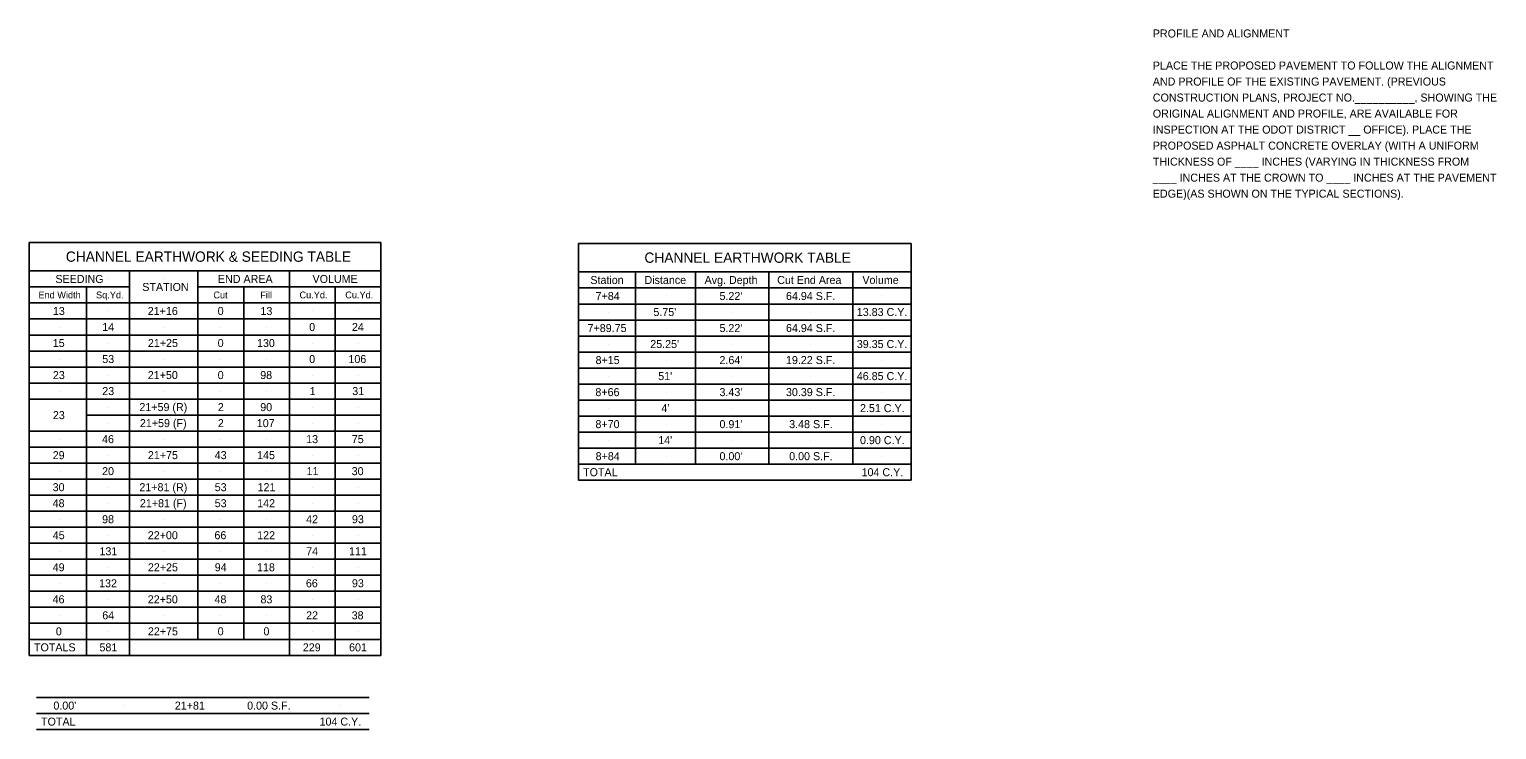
# Model space of a CAD drawing. Extents: x -30 to 76, y -31 to 50.
# Drawn here: x -29.08 to -3.41, y -12.95 to -0.71 of the extents above; entities that cross this region are included whole.
import ezdxf

# ---------------------------------------------------------------- set-up
doc = ezdxf.new("R2010")
doc.units = 0
doc.layers.add('SH_Data', color=7, linetype='Continuous')
doc.layers.add('SH_Text', color=7, linetype='Continuous')

msp = doc.modelspace()

# ---------------------------------------------------------------- linework, layer by layer
at = {"layer": 'SH_Data'}
for p, q in [((-29.076, -11.653), (-29.076, -4.433)), ((-29.076, -4.433), (-22.926, -4.433)), ((-22.926, -11.653), (-22.926, -4.433)), ((-19.47, -8.591), (-19.47, -4.451)), ((-19.47, -4.451), (-13.648, -4.451)), ((-13.648, -8.591), (-13.648, -4.451)), ((-22.926, -4.933), (-29.076, -4.933)), ((-28.707, -5.073), (-28.707, -5.073)), ((-27.692, -5.073), (-27.692, -5.073)), ((-27.326, -11.653), (-27.326, -4.933)), ((-26.726, -5.073), (-26.726, -5.073)), ((-26.126, -11.373), (-26.126, -4.933)), ((-25.326, -5.073), (-25.326, -5.073)), ((-24.526, -11.653), (-24.526, -4.933)), ((-13.648, -4.951), (-19.47, -4.951)), ((-18.951, -5.091), (-18.951, -5.091)), ((-18.472, -8.311), (-18.472, -4.951)), ((-17.936, -5.091), (-17.936, -5.091)), ((-17.42, -8.311), (-17.42, -4.951)), ((-16.781, -5.091), (-16.781, -5.091)), ((-16.14, -8.311), (-16.14, -4.951)), ((-15.419, -5.091), (-15.419, -5.091)), ((-14.669, -8.311), (-14.669, -4.951)), ((-14.169, -5.091), (-14.169, -5.091)), ((-27.326, -5.213), (-29.076, -5.213)), ((-28.557, -5.353), (-28.557, -5.353)), ((-28.077, -11.653), (-28.077, -5.213)), ((-27.692, -5.353), (-27.692, -5.353)), ((-26.726, -5.353), (-26.726, -5.353)), ((-22.926, -5.213), (-26.126, -5.213)), ((-25.326, -11.373), (-25.326, -5.213)), ((-25.025, -5.353), (-25.025, -5.353)), ((-23.726, -11.653), (-23.726, -5.213)), ((-23.425, -5.353), (-23.425, -5.353)), ((-13.648, -5.231), (-19.47, -5.231)), ((-18.951, -5.371), (-18.951, -5.371)), ((-17.936, -5.371), (-17.936, -5.371)), ((-16.781, -5.371), (-16.781, -5.371)), ((-15.419, -5.371), (-15.419, -5.371)), ((-14.169, -5.371), (-14.169, -5.371)), ((-22.926, -5.493), (-29.076, -5.493)), ((-28.557, -5.633), (-28.557, -5.633)), ((-27.692, -5.633), (-27.692, -5.633)), ((-26.726, -5.633), (-26.726, -5.633)), ((-25.726, -5.633), (-25.726, -5.633)), ((-24.926, -5.633), (-24.926, -5.633)), ((-24.126, -5.633), (-24.126, -5.633)), ((-23.326, -5.633), (-23.326, -5.633)), ((-13.648, -5.511), (-19.47, -5.511)), ((-22.926, -5.773), (-29.076, -5.773)), ((-13.648, -5.791), (-19.47, -5.791)), ((-18.951, -5.651), (-18.951, -5.651)), ((-17.936, -5.651), (-17.936, -5.651)), ((-16.781, -5.651), (-16.781, -5.651)), ((-15.419, -5.651), (-15.419, -5.651)), ((-14.169, -5.651), (-14.169, -5.651)), ((-22.926, -6.053), (-29.076, -6.053)), ((-28.557, -5.913), (-28.557, -5.913)), ((-27.692, -5.913), (-27.692, -5.913)), ((-26.726, -5.913), (-26.726, -5.913)), ((-25.726, -5.913), (-25.726, -5.913)), ((-24.926, -5.913), (-24.926, -5.913)), ((-24.126, -5.913), (-24.126, -5.913)), ((-23.326, -5.913), (-23.326, -5.913)), ((-13.648, -6.071), (-19.47, -6.071)), ((-18.951, -5.931), (-18.951, -5.931)), ((-17.936, -5.931), (-17.936, -5.931)), ((-16.781, -5.931), (-16.781, -5.931)), ((-15.419, -5.931), (-15.419, -5.931)), ((-14.169, -5.931), (-14.169, -5.931)), ((-22.926, -6.333), (-29.076, -6.333)), ((-28.557, -6.193), (-28.557, -6.193)), ((-27.692, -6.193), (-27.692, -6.193)), ((-26.726, -6.193), (-26.726, -6.193)), ((-25.726, -6.193), (-25.726, -6.193)), ((-24.926, -6.193), (-24.926, -6.193)), ((-24.126, -6.193), (-24.126, -6.193)), ((-23.326, -6.193), (-23.326, -6.193)), ((-13.648, -6.351), (-19.47, -6.351)), ((-18.951, -6.211), (-18.951, -6.211)), ((-17.936, -6.211), (-17.936, -6.211)), ((-16.781, -6.211), (-16.781, -6.211)), ((-15.419, -6.211), (-15.419, -6.211)), ((-14.169, -6.211), (-14.169, -6.211)), ((-22.926, -6.613), (-29.076, -6.613)), ((-28.557, -6.473), (-28.557, -6.473)), ((-27.692, -6.473), (-27.692, -6.473)), ((-26.726, -6.473), (-26.726, -6.473)), ((-25.726, -6.473), (-25.726, -6.473)), ((-24.926, -6.473), (-24.926, -6.473)), ((-24.126, -6.473), (-24.126, -6.473)), ((-23.326, -6.473), (-23.326, -6.473)), ((-13.648, -6.631), (-19.47, -6.631)), ((-18.951, -6.491), (-18.951, -6.491)), ((-17.936, -6.491), (-17.936, -6.491)), ((-16.781, -6.491), (-16.781, -6.491)), ((-15.419, -6.491), (-15.419, -6.491)), ((-14.169, -6.491), (-14.169, -6.491)), ((-22.926, -6.893), (-29.076, -6.893)), ((-28.557, -6.753), (-28.557, -6.753)), ((-27.692, -6.753), (-27.692, -6.753)), ((-26.726, -6.753), (-26.726, -6.753)), ((-25.726, -6.753), (-25.726, -6.753)), ((-24.926, -6.753), (-24.926, -6.753)), ((-24.126, -6.753), (-24.126, -6.753)), ((-23.326, -6.753), (-23.326, -6.753)), ((-13.648, -6.911), (-19.47, -6.911)), ((-18.951, -6.771), (-18.951, -6.771)), ((-17.936, -6.771), (-17.936, -6.771)), ((-16.781, -6.771), (-16.781, -6.771)), ((-15.419, -6.771), (-15.419, -6.771)), ((-14.169, -6.771), (-14.169, -6.771)), ((-22.926, -7.173), (-29.076, -7.173)), ((-28.557, -7.033), (-28.557, -7.033)), ((-27.692, -7.033), (-27.692, -7.033)), ((-26.726, -7.033), (-26.726, -7.033)), ((-25.726, -7.033), (-25.726, -7.033)), ((-24.926, -7.033), (-24.926, -7.033)), ((-24.126, -7.033), (-24.126, -7.033)), ((-23.326, -7.033), (-23.326, -7.033)), ((-18.951, -7.051), (-18.951, -7.051)), ((-17.936, -7.051), (-17.936, -7.051)), ((-16.781, -7.051), (-16.781, -7.051)), ((-15.419, -7.051), (-15.419, -7.051)), ((-14.169, -7.051), (-14.169, -7.051)), ((-27.692, -7.313), (-27.692, -7.313)), ((-26.726, -7.313), (-26.726, -7.313)), ((-25.726, -7.313), (-25.726, -7.313)), ((-24.926, -7.313), (-24.926, -7.313)), ((-24.126, -7.313), (-24.126, -7.313)), ((-23.326, -7.313), (-23.326, -7.313)), ((-13.648, -7.191), (-19.47, -7.191)), ((-18.951, -7.331), (-18.951, -7.331)), ((-17.936, -7.331), (-17.936, -7.331)), ((-16.781, -7.331), (-16.781, -7.331)), ((-15.419, -7.331), (-15.419, -7.331)), ((-14.169, -7.331), (-14.169, -7.331)), ((-28.557, -7.453), (-28.557, -7.453)), ((-22.926, -7.453), (-28.077, -7.453)), ((-27.692, -7.593), (-27.692, -7.593)), ((-26.726, -7.593), (-26.726, -7.593)), ((-25.726, -7.593), (-25.726, -7.593)), ((-24.926, -7.593), (-24.926, -7.593)), ((-24.126, -7.593), (-24.126, -7.593)), ((-23.326, -7.593), (-23.326, -7.593)), ((-13.648, -7.471), (-19.47, -7.471)), ((-18.951, -7.611), (-18.951, -7.611)), ((-17.936, -7.611), (-17.936, -7.611)), ((-16.781, -7.611), (-16.781, -7.611)), ((-15.419, -7.611), (-15.419, -7.611)), ((-14.169, -7.611), (-14.169, -7.611)), ((-22.926, -7.733), (-29.076, -7.733)), ((-28.557, -7.873), (-28.557, -7.873)), ((-27.692, -7.873), (-27.692, -7.873)), ((-26.726, -7.873), (-26.726, -7.873)), ((-25.726, -7.873), (-25.726, -7.873)), ((-24.926, -7.873), (-24.926, -7.873)), ((-24.126, -7.873), (-24.126, -7.873)), ((-23.326, -7.873), (-23.326, -7.873)), ((-13.648, -7.751), (-19.47, -7.751)), ((-18.951, -7.891), (-18.951, -7.891)), ((-17.936, -7.891), (-17.936, -7.891)), ((-16.781, -7.891), (-16.781, -7.891)), ((-15.419, -7.891), (-15.419, -7.891)), ((-14.169, -7.891), (-14.169, -7.891)), ((-22.926, -8.013), (-29.076, -8.013)), ((-28.557, -8.153), (-28.557, -8.153)), ((-27.692, -8.153), (-27.692, -8.153)), ((-26.726, -8.153), (-26.726, -8.153)), ((-25.726, -8.153), (-25.726, -8.153)), ((-24.926, -8.153), (-24.926, -8.153)), ((-24.126, -8.153), (-24.126, -8.153)), ((-23.326, -8.153), (-23.326, -8.153)), ((-13.648, -8.031), (-19.47, -8.031)), ((-18.951, -8.171), (-18.951, -8.171)), ((-17.936, -8.171), (-17.936, -8.171)), ((-16.781, -8.171), (-16.781, -8.171)), ((-15.419, -8.171), (-15.419, -8.171)), ((-14.169, -8.171), (-14.169, -8.171)), ((-22.926, -8.293), (-29.076, -8.293)), ((-28.557, -8.433), (-28.557, -8.433)), ((-27.692, -8.433), (-27.692, -8.433)), ((-26.726, -8.433), (-26.726, -8.433)), ((-25.726, -8.433), (-25.726, -8.433)), ((-24.926, -8.433), (-24.926, -8.433)), ((-24.126, -8.433), (-24.126, -8.433)), ((-23.326, -8.433), (-23.326, -8.433)), ((-13.648, -8.311), (-19.47, -8.311)), ((-22.926, -8.573), (-29.076, -8.573)), ((-28.557, -8.713), (-28.557, -8.713)), ((-27.692, -8.713), (-27.692, -8.713)), ((-26.726, -8.713), (-26.726, -8.713)), ((-25.726, -8.713), (-25.726, -8.713)), ((-24.926, -8.713), (-24.926, -8.713)), ((-24.126, -8.713), (-24.126, -8.713)), ((-23.326, -8.713), (-23.326, -8.713)), ((-13.648, -8.591), (-19.47, -8.591)), ((-22.926, -8.853), (-29.076, -8.853)), ((-22.926, -9.133), (-29.076, -9.133)), ((-28.557, -8.993), (-28.557, -8.993)), ((-27.692, -8.993), (-27.692, -8.993)), ((-26.726, -8.993), (-26.726, -8.993)), ((-25.726, -8.993), (-25.726, -8.993)), ((-24.926, -8.993), (-24.926, -8.993)), ((-24.126, -8.993), (-24.126, -8.993)), ((-23.326, -8.993), (-23.326, -8.993)), ((-22.926, -9.413), (-29.076, -9.413)), ((-28.557, -9.273), (-28.557, -9.273)), ((-27.692, -9.273), (-27.692, -9.273)), ((-26.726, -9.273), (-26.726, -9.273)), ((-25.726, -9.273), (-25.726, -9.273)), ((-24.926, -9.273), (-24.926, -9.273)), ((-24.126, -9.273), (-24.126, -9.273)), ((-23.326, -9.273), (-23.326, -9.273)), ((-22.926, -9.693), (-29.076, -9.693)), ((-28.557, -9.553), (-28.557, -9.553)), ((-27.692, -9.553), (-27.692, -9.553)), ((-26.726, -9.553), (-26.726, -9.553)), ((-25.726, -9.553), (-25.726, -9.553)), ((-24.926, -9.553), (-24.926, -9.553)), ((-24.126, -9.553), (-24.126, -9.553)), ((-23.326, -9.553), (-23.326, -9.553)), ((-22.926, -9.973), (-29.076, -9.973)), ((-28.557, -9.833), (-28.557, -9.833)), ((-27.692, -9.833), (-27.692, -9.833)), ((-26.726, -9.833), (-26.726, -9.833)), ((-25.726, -9.833), (-25.726, -9.833)), ((-24.926, -9.833), (-24.926, -9.833)), ((-24.126, -9.833), (-24.126, -9.833)), ((-23.326, -9.833), (-23.326, -9.833)), ((-22.926, -10.253), (-29.076, -10.253)), ((-28.557, -10.113), (-28.557, -10.113)), ((-27.692, -10.113), (-27.692, -10.113)), ((-26.726, -10.113), (-26.726, -10.113)), ((-25.726, -10.113), (-25.726, -10.113)), ((-24.926, -10.113), (-24.926, -10.113)), ((-24.126, -10.113), (-24.126, -10.113)), ((-23.326, -10.113), (-23.326, -10.113)), ((-28.557, -10.393), (-28.557, -10.393)), ((-27.692, -10.393), (-27.692, -10.393)), ((-26.726, -10.393), (-26.726, -10.393)), ((-25.726, -10.393), (-25.726, -10.393)), ((-24.926, -10.393), (-24.926, -10.393)), ((-24.126, -10.393), (-24.126, -10.393)), ((-23.326, -10.393), (-23.326, -10.393)), ((-22.926, -10.533), (-29.076, -10.533)), ((-28.557, -10.673), (-28.557, -10.673)), ((-27.692, -10.673), (-27.692, -10.673)), ((-26.726, -10.673), (-26.726, -10.673)), ((-25.726, -10.673), (-25.726, -10.673)), ((-24.926, -10.673), (-24.926, -10.673)), ((-24.126, -10.673), (-24.126, -10.673)), ((-23.326, -10.673), (-23.326, -10.673)), ((-22.926, -10.813), (-29.076, -10.813)), ((-28.557, -10.953), (-28.557, -10.953)), ((-27.692, -10.953), (-27.692, -10.953)), ((-26.726, -10.953), (-26.726, -10.953)), ((-25.726, -10.953), (-25.726, -10.953)), ((-24.926, -10.953), (-24.926, -10.953)), ((-24.126, -10.953), (-24.126, -10.953)), ((-23.326, -10.953), (-23.326, -10.953)), ((-22.926, -11.093), (-29.076, -11.093)), ((-28.557, -11.233), (-28.557, -11.233)), ((-27.692, -11.233), (-27.692, -11.233)), ((-26.726, -11.233), (-26.726, -11.233)), ((-25.726, -11.233), (-25.726, -11.233)), ((-24.926, -11.233), (-24.926, -11.233)), ((-24.126, -11.233), (-24.126, -11.233)), ((-23.326, -11.233), (-23.326, -11.233)), ((-22.926, -11.373), (-29.076, -11.373)), ((-27.692, -11.513), (-27.692, -11.513)), ((-24.126, -11.513), (-24.126, -11.513)), ((-23.326, -11.513), (-23.326, -11.513)), ((-22.926, -11.653), (-29.076, -11.653)), ((-23.13, -12.391), (-28.952, -12.391)), ((-28.433, -12.531), (-28.433, -12.531)), ((-27.418, -12.531), (-27.418, -12.531)), ((-26.263, -12.531), (-26.263, -12.531)), ((-24.901, -12.531), (-24.901, -12.531)), ((-23.651, -12.531), (-23.651, -12.531)), ((-23.13, -12.671), (-28.952, -12.671)), ((-23.13, -12.951), (-28.952, -12.951))]:
    msp.add_line(p, q, dxfattribs=at)

# ---------------------------------------------------------------- texts
for s, height, p in [('CHANNEL EARTHWORK & SEEDING TABLE', 0.18, (-28.437, -4.773)), ('CHANNEL EARTHWORK TABLE', 0.18, (-18.316, -4.791)), ('SEEDING', 0.14, (-28.62, -5.143)), ('END AREA', 0.14, (-25.777, -5.143)), ('VOLUME', 0.14, (-24.122, -5.143)), ('Station', 0.14, (-19.262, -5.161)), ('Distance', 0.14, (-18.315, -5.161)), ('Avg. Depth', 0.14, (-17.264, -5.161)), ('Cut End Area', 0.14, (-15.994, -5.161)), ('Volume', 0.14, (-14.503, -5.161)), ('End Width', 0.12, (-28.917, -5.413)), ('Sq.Yd.', 0.12, (-27.909, -5.413)), ('STATION', 0.14, (-27.1, -5.283)), ('Cut', 0.12, (-25.857, -5.413)), ('Fill', 0.12, (-25.036, -5.413)), ('Cu.Yd.', 0.12, (-24.35, -5.413)), ('Cu.Yd.', 0.12, (-23.55, -5.413)), ('7+84', 0.14, (-19.17, -5.441)), ("5.22'", 0.14, (-17.003, -5.441)), ('64.94 S.F.', 0.14, (-15.84, -5.441)), ('13', 0.14, (-28.664, -5.703)), ('21+16', 0.14, (-27.005, -5.703)), ('0', 0.14, (-25.781, -5.703)), ('13', 0.14, (-25.033, -5.703)), ("5.75'", 0.14, (-18.159, -5.721)), ('13.83 C.Y.', 0.14, (-14.601, -5.721)), ('14', 0.14, (-27.8, -5.983)), ('0', 0.14, (-24.181, -5.983)), ('24', 0.14, (-23.433, -5.983)), ('7+89.75', 0.14, (-19.311, -6.001)), ("5.22'", 0.14, (-17.003, -6.001)), ('64.94 S.F.', 0.14, (-15.84, -6.001)), ('15', 0.14, (-28.666, -6.263)), ('21+25', 0.14, (-27.002, -6.263)), ('0', 0.14, (-25.781, -6.263)), ('130', 0.14, (-25.093, -6.263)), ("25.25'", 0.14, (-18.214, -6.281)), ('39.35 C.Y.', 0.14, (-14.601, -6.281)), ('53', 0.14, (-27.8, -6.543)), ('0', 0.14, (-24.181, -6.543)), ('106', 0.14, (-23.494, -6.543)), ('8+15', 0.14, (-19.171, -6.561)), ("2.64'", 0.14, (-17.003, -6.561)), ('19.22 S.F.', 0.14, (-15.84, -6.561)), ('23', 0.14, (-28.664, -6.823)), ('21+50', 0.14, (-27.004, -6.823)), ('0', 0.14, (-25.781, -6.823)), ('98', 0.14, (-25.037, -6.823)), ("51'", 0.14, (-18.075, -6.841)), ('46.85 C.Y.', 0.14, (-14.601, -6.841)), ('23', 0.14, (-27.8, -7.103)), ('1', 0.14, (-24.172, -7.103)), ('31', 0.14, (-23.427, -7.103)), ('8+66', 0.14, (-19.174, -7.121)), ("3.43'", 0.14, (-17.003, -7.121)), ('30.39 S.F.', 0.14, (-15.84, -7.121)), ('23', 0.14, (-28.664, -7.523)), ('21+59 (R)', 0.14, (-27.151, -7.383)), ('2', 0.14, (-25.778, -7.383)), ('90', 0.14, (-25.037, -7.383)), ("4'", 0.14, (-18.019, -7.401)), ('2.51 C.Y.', 0.14, (-14.545, -7.401)), ('21+59 (F)', 0.14, (-27.142, -7.663)), ('2', 0.14, (-25.778, -7.663)), ('107', 0.14, (-25.097, -7.663)), ('8+70', 0.14, (-19.173, -7.681)), ("0.91'", 0.14, (-17.003, -7.681)), ('3.48 S.F.', 0.14, (-15.784, -7.681)), ('46', 0.14, (-27.804, -7.943)), ('13', 0.14, (-24.233, -7.943)), ('75', 0.14, (-23.435, -7.943)), ("14'", 0.14, (-18.075, -7.961)), ('0.90 C.Y.', 0.14, (-14.545, -7.961)), ('29', 0.14, (-28.667, -8.223)), ('21+75', 0.14, (-27.002, -8.223)), ('43', 0.14, (-25.833, -8.223)), ('145', 0.14, (-25.091, -8.223)), ('8+84', 0.14, (-19.17, -8.241)), ("0.00'", 0.14, (-17.003, -8.241)), ('0.00 S.F.', 0.14, (-15.784, -8.241)), ('20', 0.14, (-27.803, -8.503)), ('11', 0.14, (-24.227, -8.503)), ('30', 0.14, (-23.437, -8.503)), ('TOTAL', 0.14, (-19.389, -8.521)), ('104 C.Y.', 0.14, (-14.517, -8.521)), ('30', 0.14, (-28.668, -8.783)), ('21+81 (R)', 0.14, (-27.151, -8.783)), ('53', 0.14, (-25.833, -8.783)), ('121', 0.14, (-25.083, -8.783)), ('48', 0.14, (-28.668, -9.063)), ('21+81 (F)', 0.14, (-27.142, -9.063)), ('53', 0.14, (-25.833, -9.063)), ('142', 0.14, (-25.09, -9.063)), ('98', 0.14, (-27.803, -9.343)), ('42', 0.14, (-24.234, -9.343)), ('93', 0.14, (-23.433, -9.343)), ('45', 0.14, (-28.666, -9.623)), ('22+00', 0.14, (-27.004, -9.623)), ('66', 0.14, (-25.838, -9.623)), ('122', 0.14, (-25.09, -9.623)), ('131', 0.14, (-27.849, -9.903)), ('74', 0.14, (-24.233, -9.903)), ('111', 0.14, (-23.483, -9.903)), ('49', 0.14, (-28.667, -10.183)), ('22+25', 0.14, (-27.002, -10.183)), ('94', 0.14, (-25.833, -10.183)), ('118', 0.14, (-25.093, -10.183)), ('132', 0.14, (-27.856, -10.463)), ('66', 0.14, (-24.238, -10.463)), ('93', 0.14, (-23.433, -10.463)), ('46', 0.14, (-28.669, -10.743)), ('22+50', 0.14, (-27.004, -10.743)), ('48', 0.14, (-25.837, -10.743)), ('83', 0.14, (-25.033, -10.743)), ('64', 0.14, (-27.8, -11.023)), ('22', 0.14, (-24.234, -11.023)), ('38', 0.14, (-23.437, -11.023)), ('0', 0.14, (-28.612, -11.303)), ('22+75', 0.14, (-27.002, -11.303)), ('0', 0.14, (-25.781, -11.303)), ('0', 0.14, (-24.981, -11.303)), ('TOTALS', 0.14, (-28.995, -11.583)), ('581', 0.14, (-27.849, -11.583)), ('229', 0.14, (-24.292, -11.583)), ('601', 0.14, (-23.483, -11.583)), ("0.00'", 0.14, (-28.655, -12.601)), ('21+81', 0.14, (-26.531, -12.601)), ('0.00 S.F.', 0.14, (-25.266, -12.601)), ('TOTAL', 0.14, (-28.871, -12.881)), ('104 C.Y.', 0.14, (-23.999, -12.881))]:
    msp.add_text(s, height=height, dxfattribs=at).set_placement(p)
at = {"layer": 'SH_Text'}
for s, p in [('PROFILE AND ALIGNMENT', (-9.423, -0.852)), ('PLACE THE PROPOSED PAVEMENT TO FOLLOW THE ALIGNMENT', (-9.423, -1.412)), ('AND PROFILE OF THE EXISTING PAVEMENT. (PREVIOUS', (-9.423, -1.692)), ('CONSTRUCTION PLANS, PROJECT NO.__________, SHOWING THE', (-9.423, -1.972)), ('ORIGINAL ALIGNMENT AND PROFILE, ARE AVAILABLE FOR', (-9.423, -2.252)), ('INSPECTION AT THE ODOT DISTRICT __ OFFICE). PLACE THE', (-9.423, -2.532)), ('PROPOSED ASPHALT CONCRETE OVERLAY (WITH A UNIFORM', (-9.423, -2.812)), ('THICKNESS OF ____ INCHES (VARYING IN THICKNESS FROM', (-9.423, -3.092)), ('____ INCHES AT THE CROWN TO ____ INCHES AT THE PAVEMENT', (-9.423, -3.372)), ('EDGE)(AS SHOWN ON THE TYPICAL SECTIONS).', (-9.423, -3.652))]:
    msp.add_text(s, height=0.14, dxfattribs=at).set_placement(p)

doc.saveas('drawing.dxf')
